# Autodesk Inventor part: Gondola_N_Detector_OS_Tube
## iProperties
Shininess: 64.0
Length Units: 11272
Angle Units: 11279
Time Units: 11290
Mass Units: 11286
Length Display Precision: 3
Angle Display Precision: 2
Compacted: True
Part Number: Gondola_N_Detector_OS_Tube
Document SubType Name: Modeling
Created: 2004-12
Designer: John Blackburn
Material: Aluminum-6061
Manufacturer: Standard
Standards Organization: Custom
Density: 0.0
Volumn: 0.0
Area: 0.0
PropertySet Name: Model Information
Control State: 0
Master: False
Checked Out: False
Author: John Blackburn
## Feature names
1. Extrusion1
